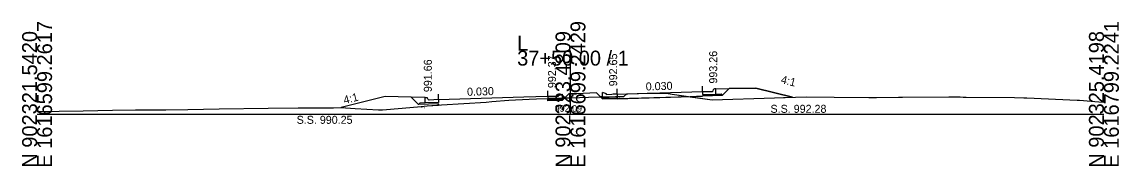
# Model space of a CAD drawing. Extents: x 1009 to 7438, y -1586 to 7964.
# Drawn here: x 3032.1 to 3237.7, y 5414 to 5441 of the extents above; entities that cross this region are included whole.
import ezdxf

# ---------------------------------------------------------------- set-up
doc = ezdxf.new("R2010")
doc.units = 0
for name, color, linetype in [('Exist Cross Section Cell', 7, 'Continuous'), ('Exist XS Center Line Elevation Label', 7, 'Continuous'), ('Exist XS Ground Line', 7, 'Continuous'), ('Prop XS Dump Level', 7, 'Continuous'), ('Prop XS Earthwork Shape', 7, 'Continuous'), ('Prop XS EOT Tick Mark', 7, 'Continuous'), ('Prop XS Finish Grade', 7, 'Continuous'), ('Prop XS Finish Grade CurbGutter', 7, 'Continuous'), ('Prop XS Finish Grade Earthwork', 7, 'Continuous'), ('Prop XS Finish Grade Pavement', 7, 'Continuous'), ('Prop XS Hydro Elevations', 7, 'Continuous'), ('Prop XS Pvmt Edge Slope', 7, 'Continuous'), ('Prop XS SE Text', 7, 'Continuous'), ('Prop XS Side Slope Text', 7, 'Continuous'), ('Prop XS SS Elevation Text', 7, 'Continuous'), ('Prop XS Subgrade CurbGutter', 7, 'Continuous'), ('Prop XS Subgrade Earthwork', 7, 'Continuous')]:
    doc.layers.add(name, color=color, linetype=linetype)

msp = doc.modelspace()

# ---------------------------------------------------------------- linework, layer by layer
at = {"layer": 'Exist Cross Section Cell'}
for p, q in [((3134.89, 5423.73), (3134.89, 5435.66)), ((3034.89, 5423.73), (3134.89, 5423.73)), ((3134.89, 5423.73), (3234.89, 5423.73))]:
    msp.add_line(p, q, dxfattribs=at)
at = {"layer": 'Exist XS Ground Line'}
for p, q in [((3110.68, 5425.48), (3119.07, 5426.01)), ((3119.07, 5426.01), (3120.16, 5426.1)), ((3120.16, 5426.1), (3123.3, 5426.37)), ((3123.3, 5426.37), (3127.13, 5426.58)), ((3127.13, 5426.58), (3128.49, 5426.65)), ((3128.49, 5426.65), (3134.89, 5426.82)), ((3134.89, 5426.82), (3138.26, 5426.92)), ((3138.26, 5426.92), (3143.31, 5427.06)), ((3143.31, 5427.06), (3144, 5427.06)), ((3144, 5427.06), (3144.89, 5427.08)), ((3144.89, 5427.08), (3145.45, 5427.58)), ((3145.45, 5427.58), (3149.24, 5427.68)), ((3149.24, 5427.68), (3150.49, 5427.71)), ((3150.49, 5427.71), (3151.44, 5427.71)), ((3151.44, 5427.71), (3152.81, 5427.7)), ((3152.81, 5427.7), (3153.97, 5427.52)), ((3153.97, 5427.52), (3161.48, 5426.43)), ((3161.48, 5426.43), (3173.11, 5426.83)), ((3173.11, 5426.83), (3179.07, 5427.03)), ((3179.07, 5427.03), (3184.33, 5426.96)), ((3184.33, 5426.96), (3190.8, 5426.87)), ((3190.8, 5426.87), (3192.24, 5426.91)), ((3192.24, 5426.91), (3196.38, 5426.93)), ((3196.38, 5426.93), (3197.11, 5426.93)), ((3197.11, 5426.93), (3205.83, 5426.99)), ((3205.83, 5426.99), (3206.36, 5426.99)), ((3206.36, 5426.99), (3207.97, 5426.98)), ((3207.97, 5426.98), (3208.53, 5426.97)), ((3208.53, 5426.97), (3209.07, 5426.96)), ((3209.07, 5426.96), (3218.1, 5426.9)), ((3218.1, 5426.9), (3219.88, 5426.82)), ((3219.88, 5426.82), (3220.42, 5426.79)), ((3220.42, 5426.79), (3229.87, 5426.38)), ((3229.87, 5426.38), (3230.34, 5426.35)), ((3230.34, 5426.35), (3233.92, 5426.06)), ((3233.92, 5426.06), (3234.89, 5425.98)), ((3034.89, 5424.27), (3039.04, 5424.33)), ((3039.04, 5424.33), (3043.51, 5424.4)), ((3043.51, 5424.4), (3049.04, 5424.51)), ((3049.04, 5424.51), (3053.32, 5424.56)), ((3053.32, 5424.56), (3059.05, 5424.57)), ((3059.05, 5424.57), (3063.13, 5424.62)), ((3063.13, 5424.62), (3069.05, 5424.75)), ((3069.05, 5424.75), (3078.2, 5424.88)), ((3078.2, 5424.88), (3083.84, 5424.97)), ((3083.84, 5424.97), (3086.94, 5424.95)), ((3086.94, 5424.95), (3088.73, 5424.94)), ((3088.73, 5424.94), (3090.46, 5424.97)), ((3090.46, 5424.97), (3091.81, 5424.99)), ((3091.81, 5424.99), (3094.54, 5424.84)), ((3094.54, 5424.84), (3098.9, 5424.58)), ((3098.9, 5424.58), (3099.31, 5424.58)), ((3099.31, 5424.58), (3099.65, 5424.58)), ((3099.65, 5424.58), (3103.32, 5424.86)), ((3103.32, 5424.86), (3106.89, 5425.2)), ((3106.89, 5425.2), (3108.05, 5425.31)), ((3108.05, 5425.31), (3110.68, 5425.48))]:
    msp.add_line(p, q, dxfattribs=at)
at = {"layer": 'Prop XS Dump Level'}
for p, q in [((3143.64, 5427.53), (3159.64, 5428.01)), ((3143.64, 5427.53), (3159.64, 5428.01)), ((3110.14, 5426.53), (3126.14, 5427.01)), ((3110.14, 5426.53), (3126.14, 5427.01)), ((3126.14, 5427.01), (3130.67, 5427.14)), ((3126.14, 5427.01), (3130.67, 5427.14))]:
    msp.add_line(p, q, dxfattribs=at)
at = {"layer": 'Prop XS Earthwork Shape'}
for points in [[(3157.34, 5427.03), (3161.48, 5426.43), (3173.11, 5426.83), (3176.48, 5426.94), (3169.64, 5428.65), (3164.64, 5428.54), (3163.39, 5427.29), (3159.64, 5427.18), (3159.64, 5427.1)], [(3110.14, 5425.61), (3110.14, 5425.7), (3106.39, 5425.58), (3105.04, 5426.94), (3100.14, 5427.04), (3091.9, 5424.98), (3094.54, 5424.84), (3098.9, 5424.58), (3099.31, 5424.58), (3099.65, 5424.58), (3103.32, 5424.86), (3106.89, 5425.2), (3108.05, 5425.31), (3110.14, 5425.44)], [(3133.17, 5426.64), (3133.42, 5426.65), (3133.42, 5426.78), (3130.66, 5426.71), (3130.67, 5426.56), (3132.17, 5426.61)], [(3130.67, 5426.31), (3130.67, 5426.56), (3132.17, 5426.61), (3133.17, 5426.64), (3133.41, 5426.39)], [(3133.41, 5426.39), (3133.81, 5426.79), (3133.42, 5426.78), (3133.42, 5426.65), (3133.17, 5426.64)], [(3139.75, 5427.76), (3136.01, 5427.58), (3134.56, 5427.55), (3133.81, 5426.79), (3134.89, 5426.82), (3138.26, 5426.92), (3140.52, 5426.98)], [(3142.14, 5426.91), (3140.9, 5426.91), (3140.9, 5426.99), (3140.52, 5426.98), (3140.88, 5426.62), (3141.14, 5426.88)], [(3143.64, 5426.7), (3143.64, 5426.95), (3142.14, 5426.91), (3141.14, 5426.88), (3140.88, 5426.62)], [(3142.14, 5426.91), (3140.9, 5426.91), (3140.9, 5426.99), (3143.31, 5427.06), (3143.64, 5427.06), (3143.64, 5426.95)], [(3143.64, 5426.7), (3143.64, 5426.95), (3143.64, 5427.06), (3144, 5427.06), (3144.89, 5427.08), (3145.45, 5427.58), (3149.24, 5427.68), (3150.49, 5427.71), (3151.44, 5427.71), (3152.81, 5427.7), (3153.97, 5427.52), (3157.34, 5427.03), (3143.64, 5426.62)]]:
    msp.add_lwpolyline(points, close=True, dxfattribs=at)
at = {"layer": 'Prop XS EOT Tick Mark'}
for p, q in [((3130.67, 5427.14), (3130.67, 5428.14)), ((3143.64, 5427.53), (3143.64, 5428.53)), ((3159.64, 5428.01), (3159.64, 5429.01)), ((3110.14, 5426.53), (3110.14, 5427.53))]:
    msp.add_line(p, q, dxfattribs=at)
at = {"layer": 'Prop XS Finish Grade'}
for p, q in [((3162.14, 5428.49), (3164.64, 5428.54)), ((3107.64, 5426.89), (3105.04, 5426.94))]:
    msp.add_line(p, q, dxfattribs=at)
at = {"layer": 'Prop XS Finish Grade CurbGutter'}
for p, q in [((3159.64, 5428.01), (3161.39, 5427.99)), ((3161.39, 5427.99), (3161.52, 5428.02)), ((3161.52, 5428.02), (3161.61, 5428.11)), ((3161.61, 5428.11), (3161.68, 5428.36)), ((3161.68, 5428.36), (3161.77, 5428.45)), ((3161.89, 5428.49), (3161.77, 5428.45)), ((3162.14, 5428.49), (3161.89, 5428.49)), ((3107.64, 5426.89), (3107.89, 5426.89)), ((3107.89, 5426.89), (3108.02, 5426.86)), ((3108.11, 5426.77), (3108.02, 5426.86)), ((3108.18, 5426.52), (3108.11, 5426.77)), ((3108.27, 5426.43), (3108.18, 5426.52)), ((3108.39, 5426.4), (3108.27, 5426.43)), ((3110.14, 5426.53), (3108.39, 5426.4)), ((3130.67, 5427.14), (3132.67, 5427.1)), ((3132.67, 5427.27), (3133.42, 5427.52)), ((3132.67, 5427.1), (3132.67, 5427.27)), ((3141.65, 5427.56), (3140.9, 5427.81)), ((3141.65, 5427.39), (3141.65, 5427.56)), ((3143.64, 5427.53), (3141.65, 5427.39)), ((3143.64, 5427.53), (3142.89, 5427.48))]:
    msp.add_line(p, q, dxfattribs=at)
at = {"layer": 'Prop XS Finish Grade Earthwork'}
for p, q in [((3164.64, 5428.54), (3169.64, 5428.65)), ((3169.64, 5428.65), (3176.48, 5426.94)), ((3100.14, 5427.04), (3091.9, 5424.98)), ((3105.04, 5426.94), (3100.14, 5427.04)), ((3134.56, 5427.55), (3136.01, 5427.58)), ((3139.75, 5427.76), (3136.01, 5427.58))]:
    msp.add_line(p, q, dxfattribs=at)
at = {"layer": 'Prop XS Finish Grade Pavement'}
for p, q in [((3143.64, 5427.53), (3159.64, 5428.01)), ((3110.14, 5426.53), (3126.14, 5427.01)), ((3126.14, 5427.01), (3130.67, 5427.14))]:
    msp.add_line(p, q, dxfattribs=at)
at = {"layer": 'Prop XS Pvmt Edge Slope'}
for p, q in [((3132.17, 5426.61), (3133.42, 5426.65)), ((3132.17, 5426.61), (3133.17, 5426.64)), ((3133.17, 5426.64), (3133.41, 5426.39)), ((3141.14, 5426.88), (3140.88, 5426.62)), ((3142.14, 5426.91), (3140.9, 5426.91)), ((3142.14, 5426.91), (3141.14, 5426.88)), ((3162.14, 5427.51), (3163.14, 5427.54)), ((3163.14, 5427.54), (3163.39, 5427.29)), ((3106.64, 5425.84), (3106.39, 5425.58)), ((3107.64, 5425.87), (3106.64, 5425.84))]:
    msp.add_line(p, q, dxfattribs=at)
at = {"layer": 'Prop XS Subgrade CurbGutter'}
for p, q in [((3159.64, 5428.01), (3159.64, 5427.43)), ((3162.14, 5427.51), (3162.14, 5428.49)), ((3107.64, 5425.87), (3107.64, 5426.89)), ((3110.14, 5425.95), (3107.64, 5425.87)), ((3110.14, 5426.53), (3110.14, 5425.95)), ((3130.67, 5427.14), (3130.67, 5426.56)), ((3130.67, 5426.56), (3132.17, 5426.61)), ((3133.42, 5426.65), (3133.42, 5427.52)), ((3140.9, 5426.91), (3140.9, 5427.81)), ((3143.64, 5426.95), (3142.14, 5426.91)), ((3143.64, 5427.53), (3143.64, 5426.95)), ((3159.64, 5427.43), (3162.14, 5427.51))]:
    msp.add_line(p, q, dxfattribs=at)
at = {"layer": 'Prop XS Subgrade Earthwork'}
for p, q in [((3163.39, 5427.29), (3164.64, 5428.54)), ((3106.39, 5425.58), (3105.04, 5426.94)), ((3130.67, 5426.23), (3130.66, 5426.71)), ((3130.67, 5426.31), (3133.41, 5426.39)), ((3130.67, 5426.23), (3130.67, 5426.31)), ((3133.41, 5426.39), (3134.56, 5427.55)), ((3140.88, 5426.62), (3139.75, 5427.76)), ((3143.64, 5426.7), (3140.88, 5426.62)), ((3143.64, 5426.62), (3159.64, 5427.1)), ((3143.64, 5426.62), (3143.64, 5427.06)), ((3143.64, 5426.62), (3143.64, 5427.06)), ((3143.64, 5426.62), (3143.64, 5426.7)), ((3159.64, 5427.18), (3163.39, 5427.29)), ((3159.64, 5427.1), (3159.64, 5427.18)), ((3110.14, 5425.7), (3106.39, 5425.58)), ((3110.14, 5425.61), (3110.14, 5425.7)), ((3110.14, 5425.61), (3110.14, 5425.44))]:
    msp.add_line(p, q, dxfattribs=at)

# ---------------------------------------------------------------- texts
at = {"layer": 'Exist Cross Section Cell'}
for s, p in [('E 1616599.2617', (3037.69, 5413.73)), ('E 1616699.2429', (3137.69, 5413.73)), ('E 1616799.2241', (3237.69, 5413.73)), ('N 902321.5420', (3034.89, 5413.73)), ('N 902323.4809', (3134.89, 5413.73)), ('N 902325.4198', (3234.89, 5413.73))]:
    msp.add_text(s, height=2.8, rotation=90, dxfattribs=at).set_placement(p)
for s, p in [('L', (3124.89, 5435.66)), ('37+50.00 / 1', (3124.89, 5432.86))]:
    msp.add_text(s, height=2.8, dxfattribs=at).set_placement(p)
at = {"layer": 'Exist XS Center Line Elevation Label'}
msp.add_text('992.09', height=1.25, dxfattribs=at).set_placement((3131.94, 5424.2))
at = {"layer": 'Prop XS Dump Level'}
for p in [(3143.31, 5426.76), (3143.31, 5426.76), (3143.31, 5426.76), (3106.91, 5424.9)]:
    msp.add_text('Eop', height=0.3, dxfattribs=at).set_placement(p)
at = {"layer": 'Prop XS Hydro Elevations'}
for s, p in [('992.37', (3132.17, 5428.64)), ('992.65', (3143.64, 5428.98)), ('993.26', (3162.39, 5429.49)), ('991.66', (3108.89, 5427.89))]:
    msp.add_text(s, height=1.5, rotation=90, dxfattribs=at).set_placement(p)
at = {"layer": 'Prop XS SE Text'}
for p in [(3115.52, 5427.19), (3149.02, 5428.19)]:
    msp.add_text('0.030', height=1.5, rotation=1.7184, dxfattribs=at).set_placement(p)
at = {"layer": 'Prop XS Side Slope Text'}
for rotation, p in [(345.9638, (3174.23, 5429.59)), (14.0362, (3092.53, 5425.64))]:
    msp.add_text('4:1', height=1.5, rotation=rotation, dxfattribs=at).set_placement(p)
at = {"layer": 'Prop XS SS Elevation Text'}
for s, p in [('S.S. 992.28', (3172.39, 5424.01)), ('S.S. 990.25', (3083.55, 5421.95))]:
    msp.add_text(s, height=1.5, dxfattribs=at).set_placement(p)

doc.saveas('drawing.dxf')
